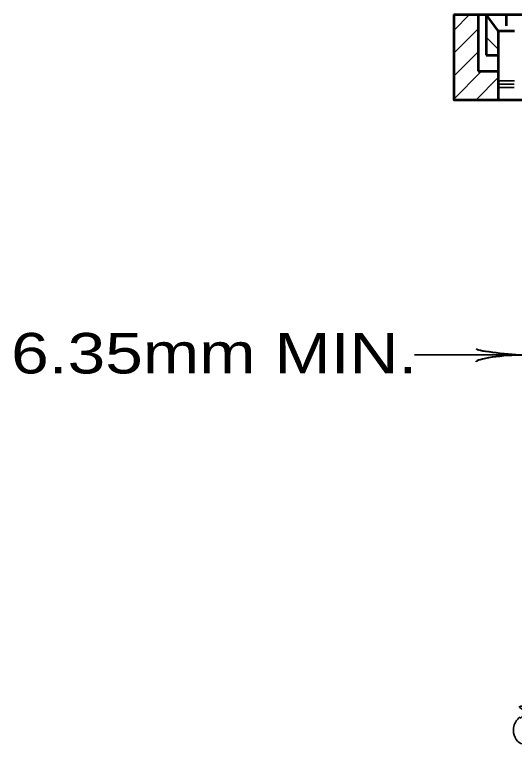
# Model space of a CAD drawing. Extents: x 442 to 1297, y -1132 to -588.
# Drawn here: x 1009.9 to 1046.9, y -928.8 to -874.7 of the extents above; entities that cross this region are included whole.
import ezdxf

# ---------------------------------------------------------------- set-up
doc = ezdxf.new("R2010")
doc.units = 0
doc.header["$LTSCALE"] = 0.96
doc.layers.add('1', color=7, linetype='Continuous', lineweight=35)

msp = doc.modelspace()

# ---------------------------------------------------------------- linework, layer by layer
at = {"layer": '1'}
for p, q in [((1042.454, -875.8277), (1043.62, -874.6617)), ((1042.454, -877.5248), (1044.254, -875.7247)), ((1045.754, -877.224), (1044.854, -876.324)), ((1042.454, -879.2218), (1044.254, -877.4219)), ((1042.4113, -880.9617), (1044.5112, -878.8617)), ((1044.1083, -880.9617), (1045.754, -879.3159)), ((1045.7332, -879.8162), (1046.9358, -879.8162)), ((1045.7529, -879.5589), (1046.9555, -879.5589)), ((1045.7332, -880.0717), (1046.9358, -880.0717)), ((1039.5476, -899.8686), (1047.554, -899.8686))]:
    msp.add_line(p, q, dxfattribs=at)
at = {"layer": '1', "lineweight": 53}
for p, q in [((1044.254, -874.6617), (1044.254, -878.8617)), ((1044.854, -874.6617), (1044.854, -877.6617)), ((1045.754, -875.8617), (1044.854, -874.6617)), ((1046.354, -875.5017), (1046.354, -874.6617)), ((1045.754, -875.8617), (1046.954, -875.8617)), ((1044.854, -877.6617), (1045.7556, -877.6617)), ((1044.254, -878.8617), (1045.754, -878.8617))]:
    msp.add_line(p, q, dxfattribs=at)
for points in [[(1042.454, -874.6617), (1105.154, -874.6617), (1105.154, -880.9617)], [(1042.454, -874.6617), (1042.454, -880.9617), (1047.554, -880.9617)], [(1045.754, -875.8617), (1045.754, -878.8617), (1045.754, -880.9617)]]:
    msp.add_lwpolyline(points, dxfattribs=at)
at = {"layer": '1', "lineweight": 40}
for centre, major_axis, ratio, start_param, end_param in [((1046.2094, -899.6147), (2.1077, -0.2108), 0.07063, 3.1407148, 5.41811), ((1046.2446, -900.2002), (2.1428, 0.1874), 0.122415, 0.8963533, 3.1415927)]:
    msp.add_ellipse(centre, major_axis=major_axis, ratio=ratio, start_param=start_param, end_param=end_param, dxfattribs=at)
at = {"layer": '1'}
for points in [[(1049.5895, -923.3546), (1049.4692, -923.7756), (1048.988, -924.6778), (1048.2662, -925.7004), (1047.7249, -925.8808), (1047.4241, -925.8808), (1049.5293, -926.7831), (1050.612, -926.6026), (1051.2135, -925.941), (1051.3939, -925.0387), (1050.8526, -924.317), (1050.612, -923.4749), (1049.9504, -923.2343), (1049.2887, -923.2944)], [(1047.3521, -926.6616), (1046.8709, -927.5036), (1047.4122, -928.6465), (1048.7355, -927.9848), (1049.5174, -927.3232), (1049.4573, -926.7819), (1048.0137, -926.7217), (1047.5325, -926.6616), (1047.3521, -926.7819)]]:
    msp.add_spline(points, degree=3, dxfattribs=at)

# ---------------------------------------------------------------- texts
at = {"layer": '1', "width": 1.25}
msp.add_text('6.35mm MIN.', height=3, dxfattribs=at).set_placement((1009.6456, -901.2392))

doc.saveas('drawing.dxf')
